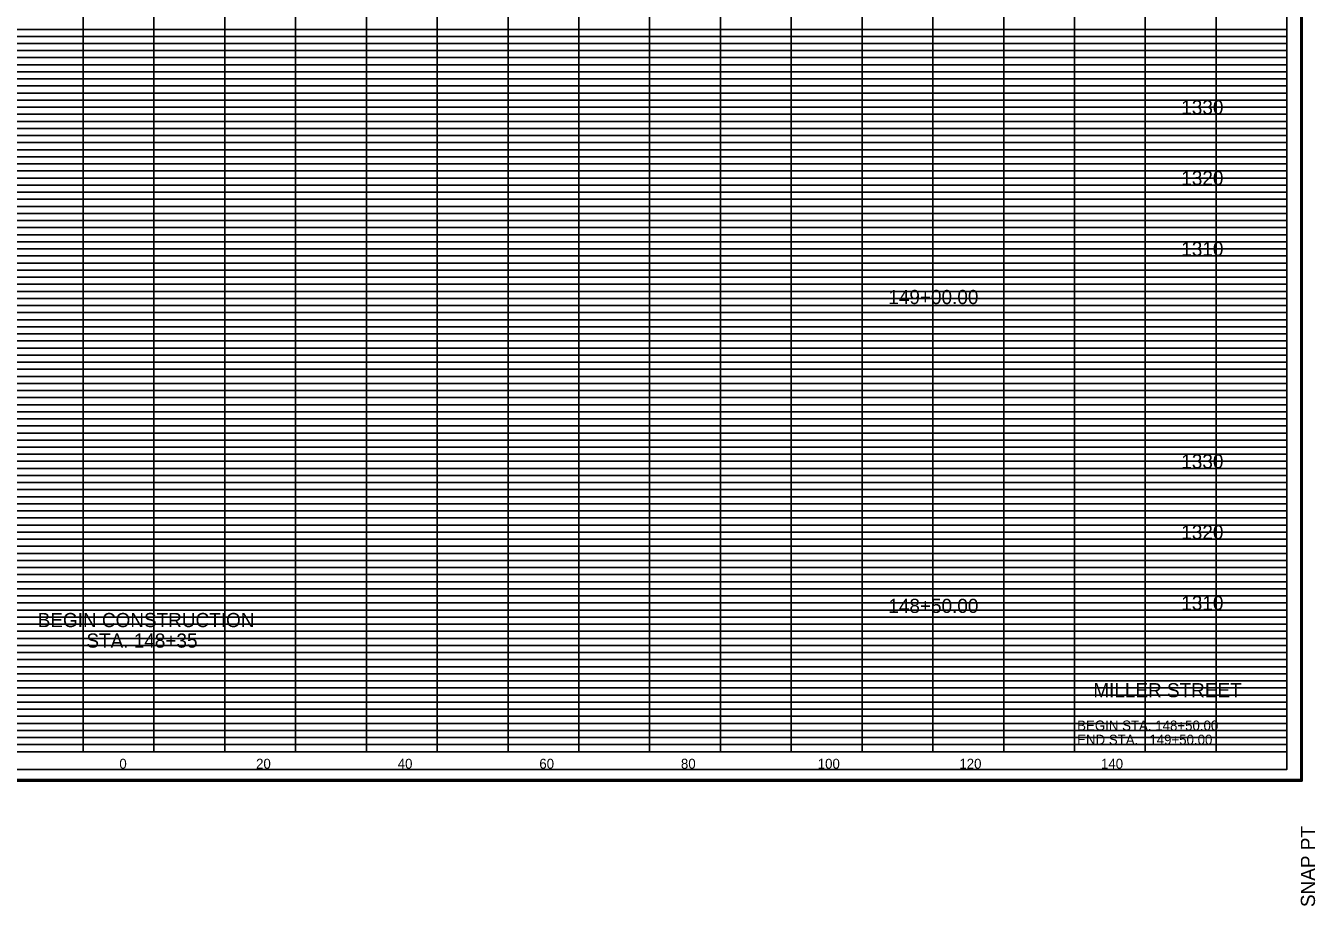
# Model space of a CAD drawing. Extents: x 980 to 1324, y 978 to 1227.
# Drawn here: x 1141.7 to 1323.8, y 978 to 1102.3 of the extents above; entities that cross this region are included whole.
import ezdxf

# ---------------------------------------------------------------- set-up
doc = ezdxf.new("R2010")
doc.units = 0
for name, color, linetype in [('Default', 7, 'Continuous'), ('DESIGN - SHEET - Corner Text', 7, 'Continuous'), ('DESIGN - SHEET - Light Grid', 7, 'Continuous'), ('DESIGN - SHEET - Linework', 7, 'Continuous'), ('DESIGN - SHEET - Plot Shape', 7, 'Continuous'), ('DESIGN - TYPICAL - Text', 7, 'Continuous')]:
    doc.layers.add(name, color=color, linetype=linetype)

# ---------------------------------------------------------------- blocks, each defined once
blk = doc.blocks.new('XSTSHT')
at = {"layer": 'DESIGN - SHEET - Light Grid'}
for p, q in [((8, 10.2), (16, 10.2)), ((16, 10.2), (24, 10.2)), ((24, 10.2), (32, 10.2)), ((8, 10.1), (16, 10.1)), ((16, 10.1), (24, 10.1)), ((24, 10.1), (32, 10.1)), ((8, 9.9), (16, 9.9)), ((16, 9.9), (24, 9.9)), ((24, 9.9), (32, 9.9)), ((8, 9.8), (16, 9.8)), ((8, 9.7), (16, 9.7)), ((16, 9.8), (24, 9.8)), ((16, 9.7), (24, 9.7)), ((24, 9.8), (32, 9.8)), ((24, 9.7), (32, 9.7)), ((8, 9.6), (16, 9.6)), ((8, 9.5), (16, 9.5)), ((16, 9.6), (24, 9.6)), ((16, 9.5), (24, 9.5)), ((24, 9.6), (32, 9.6)), ((24, 9.5), (32, 9.5)), ((8, 9.4), (16, 9.4)), ((8, 9.3), (16, 9.3)), ((16, 9.4), (24, 9.4)), ((16, 9.3), (24, 9.3)), ((24, 9.4), (32, 9.4)), ((24, 9.3), (32, 9.3)), ((8, 9.2), (16, 9.2)), ((16, 9.2), (24, 9.2)), ((24, 9.2), (32, 9.2)), ((8, 9.1), (16, 9.1)), ((16, 9.1), (24, 9.1)), ((24, 9.1), (32, 9.1)), ((8, 8.9), (16, 8.9)), ((8, 8.8), (16, 8.8)), ((16, 8.9), (24, 8.9)), ((16, 8.8), (24, 8.8)), ((24, 8.9), (32, 8.9)), ((24, 8.8), (32, 8.8)), ((8, 8.7), (16, 8.7)), ((8, 8.6), (16, 8.6)), ((16, 8.7), (24, 8.7)), ((16, 8.6), (24, 8.6)), ((24, 8.7), (32, 8.7)), ((24, 8.6), (32, 8.6)), ((8, 8.5), (16, 8.5)), ((8, 8.4), (16, 8.4)), ((16, 8.5), (24, 8.5)), ((16, 8.4), (24, 8.4)), ((24, 8.5), (32, 8.5)), ((24, 8.4), (32, 8.4)), ((8, 8.3), (16, 8.3)), ((8, 8.2), (16, 8.2)), ((16, 8.3), (24, 8.3)), ((16, 8.2), (24, 8.2)), ((24, 8.3), (32, 8.3)), ((24, 8.2), (32, 8.2)), ((8, 8.1), (16, 8.1)), ((16, 8.1), (24, 8.1)), ((24, 8.1), (32, 8.1)), ((8, 7.9), (16, 7.9)), ((16, 7.9), (24, 7.9)), ((24, 7.9), (32, 7.9)), ((8, 7.8), (16, 7.8)), ((8, 7.7), (16, 7.7)), ((16, 7.8), (24, 7.8)), ((16, 7.7), (24, 7.7)), ((24, 7.8), (32, 7.8)), ((24, 7.7), (32, 7.7)), ((8, 7.6), (16, 7.6)), ((8, 7.5), (16, 7.5)), ((16, 7.6), (24, 7.6)), ((16, 7.5), (24, 7.5)), ((24, 7.6), (32, 7.6)), ((24, 7.5), (32, 7.5)), ((8, 7.4), (16, 7.4)), ((8, 7.3), (16, 7.3)), ((16, 7.4), (24, 7.4)), ((16, 7.3), (24, 7.3)), ((24, 7.4), (32, 7.4)), ((24, 7.3), (32, 7.3)), ((8, 7.2), (16, 7.2)), ((16, 7.2), (24, 7.2)), ((24, 7.2), (32, 7.2)), ((8, 7.1), (16, 7.1)), ((16, 7.1), (24, 7.1)), ((24, 7.1), (32, 7.1)), ((8, 6.9), (16, 6.9)), ((8, 6.8), (16, 6.8)), ((16, 6.9), (24, 6.9)), ((16, 6.8), (24, 6.8)), ((24, 6.9), (32, 6.9)), ((24, 6.8), (32, 6.8)), ((8, 6.7), (16, 6.7)), ((8, 6.6), (16, 6.6)), ((16, 6.7), (24, 6.7)), ((16, 6.6), (24, 6.6)), ((24, 6.7), (32, 6.7)), ((24, 6.6), (32, 6.6)), ((8, 6.5), (16, 6.5)), ((8, 6.4), (16, 6.4)), ((16, 6.5), (24, 6.5)), ((16, 6.4), (24, 6.4)), ((24, 6.5), (32, 6.5)), ((24, 6.4), (32, 6.4)), ((8, 6.3), (16, 6.3)), ((8, 6.2), (16, 6.2)), ((16, 6.3), (24, 6.3)), ((16, 6.2), (24, 6.2)), ((24, 6.3), (32, 6.3)), ((24, 6.2), (32, 6.2)), ((8, 6.1), (16, 6.1)), ((16, 6.1), (24, 6.1)), ((24, 6.1), (32, 6.1)), ((8, 5.9), (16, 5.9)), ((16, 5.9), (24, 5.9)), ((24, 5.9), (32, 5.9)), ((8, 5.8), (16, 5.8)), ((8, 5.7), (16, 5.7)), ((16, 5.8), (24, 5.8)), ((16, 5.7), (24, 5.7)), ((24, 5.8), (32, 5.8)), ((24, 5.7), (32, 5.7)), ((8, 5.6), (16, 5.6)), ((8, 5.5), (16, 5.5)), ((16, 5.6), (24, 5.6)), ((16, 5.5), (24, 5.5)), ((24, 5.6), (32, 5.6)), ((24, 5.5), (32, 5.5)), ((8, 5.4), (16, 5.4)), ((8, 5.3), (16, 5.3)), ((16, 5.4), (24, 5.4)), ((16, 5.3), (24, 5.3)), ((24, 5.4), (32, 5.4)), ((24, 5.3), (32, 5.3)), ((8, 5.2), (16, 5.2)), ((8, 5.1), (16, 5.1)), ((16, 5.2), (24, 5.2)), ((16, 5.1), (24, 5.1)), ((24, 5.2), (32, 5.2)), ((24, 5.1), (32, 5.1)), ((8, 4.9), (16, 4.9)), ((8, 4.8), (16, 4.8)), ((16, 4.9), (24, 4.9)), ((16, 4.8), (24, 4.8)), ((24, 4.9), (32, 4.9)), ((24, 4.8), (32, 4.8)), ((8, 4.7), (16, 4.7)), ((8, 4.6), (16, 4.6)), ((16, 4.7), (24, 4.7)), ((16, 4.6), (24, 4.6)), ((24, 4.7), (32, 4.7)), ((24, 4.6), (32, 4.6)), ((8, 4.5), (16, 4.5)), ((8, 4.4), (16, 4.4)), ((16, 4.5), (24, 4.5)), ((16, 4.4), (24, 4.4)), ((24, 4.5), (32, 4.5)), ((24, 4.4), (32, 4.4)), ((8, 4.3), (16, 4.3)), ((8, 4.2), (16, 4.2)), ((16, 4.3), (24, 4.3)), ((16, 4.2), (24, 4.2)), ((24, 4.3), (32, 4.3)), ((24, 4.2), (32, 4.2)), ((8, 4.1), (16, 4.1)), ((16, 4.1), (24, 4.1)), ((24, 4.1), (32, 4.1)), ((8, 3.9), (16, 3.9)), ((16, 3.9), (24, 3.9)), ((24, 3.9), (32, 3.9)), ((8, 3.8), (16, 3.8)), ((8, 3.7), (16, 3.7)), ((16, 3.8), (24, 3.8)), ((16, 3.7), (24, 3.7)), ((24, 3.8), (32, 3.8)), ((24, 3.7), (32, 3.7)), ((8, 3.6), (16, 3.6)), ((8, 3.5), (16, 3.5)), ((16, 3.6), (24, 3.6)), ((16, 3.5), (24, 3.5)), ((24, 3.6), (32, 3.6)), ((24, 3.5), (32, 3.5)), ((8, 3.4), (16, 3.4)), ((8, 3.3), (16, 3.3)), ((16, 3.4), (24, 3.4)), ((16, 3.3), (24, 3.3)), ((24, 3.4), (32, 3.4)), ((24, 3.3), (32, 3.3)), ((8, 3.2), (16, 3.2)), ((8, 3.1), (16, 3.1)), ((16, 3.2), (24, 3.2)), ((16, 3.1), (24, 3.1)), ((24, 3.2), (32, 3.2)), ((24, 3.1), (32, 3.1)), ((8, 2.9), (16, 2.9)), ((8, 2.8), (16, 2.8)), ((16, 2.9), (24, 2.9)), ((16, 2.8), (24, 2.8)), ((24, 2.9), (32, 2.9)), ((24, 2.8), (32, 2.8)), ((8, 2.7), (16, 2.7)), ((8, 2.6), (16, 2.6)), ((16, 2.7), (24, 2.7)), ((16, 2.6), (24, 2.6)), ((24, 2.7), (32, 2.7)), ((24, 2.6), (32, 2.6)), ((8, 2.5), (16, 2.5)), ((8, 2.4), (16, 2.4)), ((16, 2.5), (24, 2.5)), ((16, 2.4), (24, 2.4)), ((24, 2.5), (32, 2.5)), ((24, 2.4), (32, 2.4)), ((8, 2.3), (16, 2.3)), ((8, 2.2), (16, 2.2)), ((16, 2.3), (24, 2.3)), ((16, 2.2), (24, 2.2)), ((24, 2.3), (32, 2.3)), ((24, 2.2), (32, 2.2)), ((8, 2.1), (16, 2.1)), ((16, 2.1), (24, 2.1)), ((24, 2.1), (32, 2.1)), ((8, 1.9), (16, 1.9)), ((16, 1.9), (24, 1.9)), ((24, 1.9), (32, 1.9)), ((8, 1.8), (16, 1.8)), ((8, 1.7), (16, 1.7)), ((16, 1.8), (24, 1.8)), ((16, 1.7), (24, 1.7)), ((24, 1.8), (32, 1.8)), ((24, 1.7), (32, 1.7)), ((8, 1.6), (16, 1.6)), ((8, 1.5), (16, 1.5)), ((16, 1.6), (24, 1.6)), ((16, 1.5), (24, 1.5)), ((24, 1.6), (32, 1.6)), ((24, 1.5), (32, 1.5)), ((8, 1.4), (16, 1.4)), ((8, 1.3), (16, 1.3)), ((16, 1.4), (24, 1.4)), ((16, 1.3), (24, 1.3)), ((24, 1.4), (32, 1.4)), ((24, 1.3), (32, 1.3)), ((8, 1.2), (16, 1.2)), ((8, 1.1), (16, 1.1)), ((16, 1.2), (24, 1.2)), ((16, 1.1), (24, 1.1)), ((24, 1.2), (32, 1.2)), ((24, 1.1), (32, 1.1)), ((8, 0.9), (16, 0.9)), ((8, 0.8), (16, 0.8)), ((16, 0.9), (24, 0.9)), ((16, 0.8), (24, 0.8)), ((24, 0.9), (32, 0.9)), ((24, 0.8), (32, 0.8)), ((8, 0.7), (16, 0.7)), ((8, 0.6), (16, 0.6)), ((16, 0.7), (24, 0.7)), ((16, 0.6), (24, 0.6)), ((24, 0.7), (32, 0.7)), ((24, 0.6), (32, 0.6)), ((8, 0.5), (16, 0.5)), ((8, 0.4), (16, 0.4)), ((16, 0.5), (24, 0.5)), ((16, 0.4), (24, 0.4)), ((24, 0.5), (32, 0.5)), ((24, 0.4), (32, 0.4)), ((8, 0.3), (16, 0.3)), ((8, 0.2), (16, 0.2)), ((16, 0.3), (24, 0.3)), ((16, 0.2), (24, 0.2)), ((24, 0.3), (32, 0.3)), ((24, 0.2), (32, 0.2)), ((8, 0.1), (16, 0.1)), ((16, 0.1), (24, 0.1)), ((24, 0.1), (32, 0.1))]:
    blk.add_line(p, q, dxfattribs=at)
at = {"layer": 'DESIGN - SHEET - Linework'}
for p, q in [((32.217, 21.414), (32.217, -0.414)), ((15, 0), (15, 21)), ((16, 0), (16, 21)), ((17, 0), (17, 21)), ((18, 0), (18, 21)), ((19, 0), (19, 21)), ((20, 0), (20, 21)), ((21, 0), (21, 21)), ((22, 0), (22, 21)), ((23, 0), (23, 21)), ((24, 0), (24, 21)), ((25, 0), (25, 21)), ((26, 0), (26, 21)), ((27, 0), (27, 21)), ((28, 0), (28, 20)), ((29, 0), (29, 20)), ((30, 0), (30, 20)), ((31, 0), (31, 20)), ((0, 10), (32, 10)), ((0, 9), (32, 9)), ((0, 8), (32, 8)), ((0, 7), (32, 7)), ((0, 6), (32, 6)), ((0, 5), (32, 5)), ((0, 4), (32, 4)), ((0, 3), (32, 3)), ((0, 2), (32, 2)), ((0, 1), (32, 1)), ((-1.823, -0.414), (32.217, -0.414))]:
    blk.add_line(p, q, dxfattribs=at)
blk.add_lwpolyline([(0, 21), (0, 0), (32, 0), (32, 21), (0, 21)], dxfattribs=at)
at = {"layer": 'DESIGN - SHEET - Plot Shape'}
for points in [[(-1.803, 21.394), (32.197, 21.394), (32.197, -0.394), (-1.803, -0.394)], [(-0.85, 21), (32, 21), (32, -0.25), (-0.85, -0.25)]]:
    blk.add_lwpolyline(points, close=True, dxfattribs=at)
at = {"layer": 'DESIGN - SHEET - Corner Text'}
blk.add_text('SNAP PT  ', height=0.2, rotation=90, dxfattribs=at).set_placement((32.397, -2.194))

msp = doc.modelspace()

# ---------------------------------------------------------------- linework, layer by layer
at = {"layer": 'DESIGN - SHEET - Plot Shape'}
msp.add_lwpolyline([(991.3, 997.3), (1319.8, 997.3), (1319.8, 1209.8), (991.3, 1209.8)], close=True, dxfattribs=at)

# ---------------------------------------------------------------- block references
at = {"layer": 'Default', "xscale": 10, "yscale": 10}
msp.add_blockref('XSTSHT', (999.8, 999.8), dxfattribs=at)

# ---------------------------------------------------------------- texts
at = {"layer": 'DESIGN - SHEET - Corner Text'}
for s, height, p in [('MILLER STREET', 2, (1292.46, 1007.48)), ('BEGIN STA. 148+50.00', 1.4, (1290.18, 1002.8)), ('END STA.   149+50.00', 1.4, (1290.18, 1000.8))]:
    msp.add_text(s, height=height, dxfattribs=at).set_placement(p)
at = {"layer": 'DESIGN - TYPICAL - Text'}
for s, height, p in [('     1330     ', 2, (1301.17, 1089.8)), ('     1320     ', 2, (1301.17, 1079.8)), ('     1310     ', 2, (1301.17, 1069.8)), ('     149+00.00     ', 2, (1259.8, 1063)), ('     1330     ', 2, (1301.17, 1039.8)), ('     1320     ', 2, (1301.17, 1029.8)), ('     1310     ', 2, (1301.17, 1019.8)), ('     148+50.00     ', 2, (1259.8, 1019.39)), ('BEGIN CONSTRUCTION', 2, (1143.38, 1017.39)), ('STA. 148+35', 2, (1150.26, 1014.49)), ('     0     ', 1.4, (1152.31, 997.4)), ('     0     ', 1.4, (1152.31, 997.4)), ('     0     ', 1.4, (1152.31, 997.4)), ('     0     ', 1.4, (1152.31, 997.4)), ('     20     ', 1.4, (1171.62, 997.4)), ('     20     ', 1.4, (1171.62, 997.4)), ('     40     ', 1.4, (1191.62, 997.4)), ('     40     ', 1.4, (1191.62, 997.4)), ('     60     ', 1.4, (1211.62, 997.4)), ('     60     ', 1.4, (1211.62, 997.4)), ('     80     ', 1.4, (1231.62, 997.4)), ('     80     ', 1.4, (1231.62, 997.4)), ('     100     ', 1.4, (1250.94, 997.4)), ('     100     ', 1.4, (1250.94, 997.4)), ('     120     ', 1.4, (1270.94, 997.4)), ('     120     ', 1.4, (1270.94, 997.4)), ('     140     ', 1.4, (1290.94, 997.4)), ('     140     ', 1.4, (1290.94, 997.4))]:
    msp.add_text(s, height=height, dxfattribs=at).set_placement(p)

doc.saveas('drawing.dxf')
